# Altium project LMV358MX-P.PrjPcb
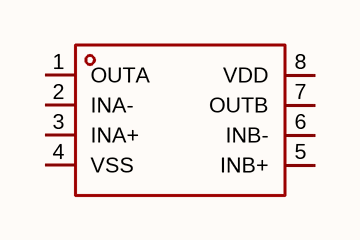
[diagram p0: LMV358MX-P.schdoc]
1 sheet, 1 parts. Net scope: global (net labels, ports and power ports of the same name join across sheets).

## Sheet LMV358MX-P.schdoc
size 127 x 101 mm

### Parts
U?  lmv358mx-p  [SOP-8_L4.9-W3.9-P1.27-LS6.0-BL]  (value not drawn)

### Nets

Not connected (* = marked no-connect by the designer): U? 1(OUTA) 2(INA-) 3(INA+) 4(VSS) 5(INB+) 6(INB-) 7(OUTB) 8(VDD)

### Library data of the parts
U? = lmv358mx-p: 放大器数:2;轨到轨:轨到轨输入,轨到轨输出;增益带宽积(GBW):1MHz;输入失调电压(Vos):5mV;压摆率(SR):600V/ms;输入偏置电流(Ib):10pA;; Manufacturer: TECH PUBLIC(台舟); AddInBom: yes; ModelId: 75c24a7891ee4dd6bdac16a7163ff87e; ModelName: SOP-8_L4.9-W3.9-P1.27-LS6.0-BL-1; ModelTransform: 192.913,236.22,0,0,0,0,-0.393,2.749,0; Number of Channels: 2; Maximum Power Supply Range (Vdd-Vss): 7V; Gain Bandwidth Product: 1MHz; Vos - Input Offset Voltage: 5mV; Input Offset Voltage Drift(Vos TC): 2uV/℃; Ib - Input Bias Current: 10pA; Input Voltage Noise Density: 20nV/√Hz@10kHz; Common Mode Rejection Ratio(CMRR): 80dB; Quiescent Current: 40uA; Output Current: 20mA; Single supply: 2.5V~5.5V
